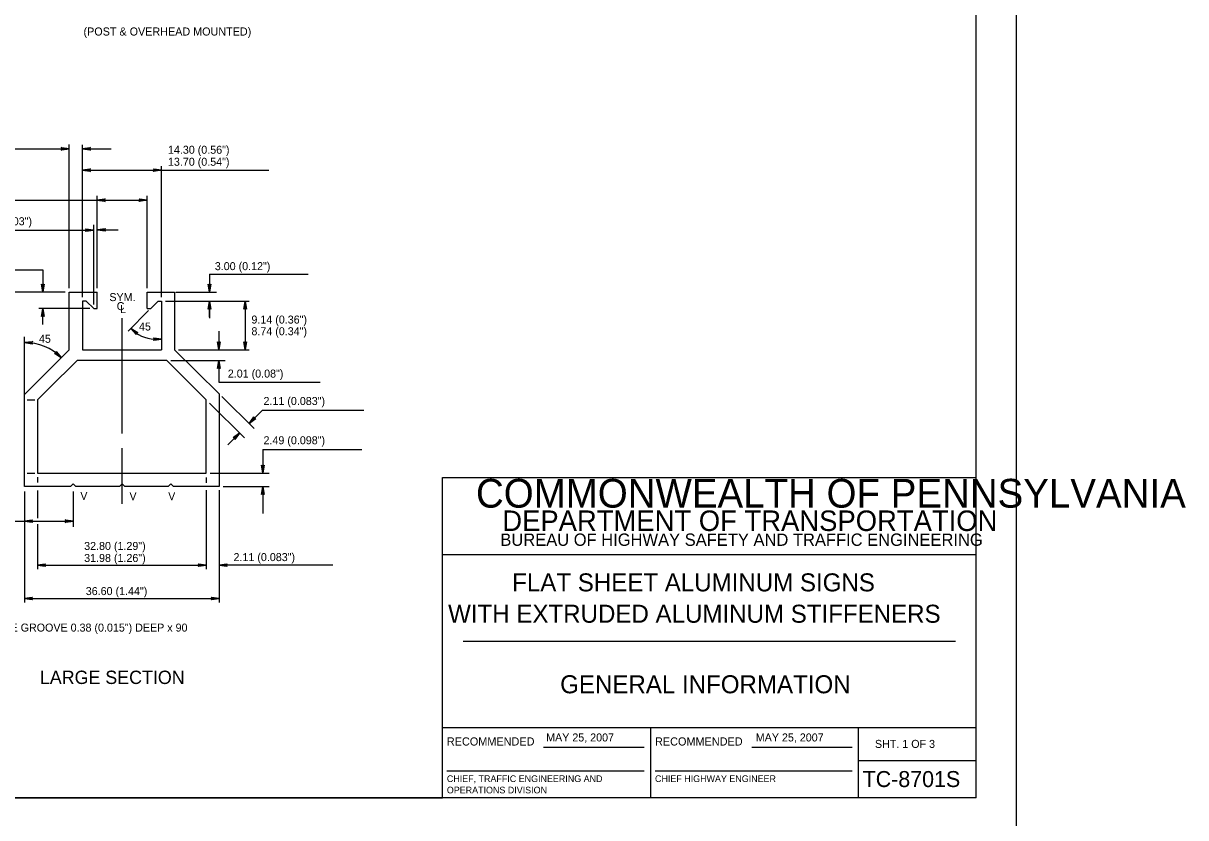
# Model space of a CAD drawing. Extents: x 650495 to 651400, y 297864 to 299646.
# Drawn here: x 650964.3 to 651399.9, y 299059.1 to 299356.9 of the extents above; entities that cross this region are included whole.
import ezdxf

# ---------------------------------------------------------------- set-up
doc = ezdxf.new("R2010")
doc.units = 0
for name, color, linetype in [('1', 7, 'Continuous'), ('2', 7, 'Continuous'), ('3', 7, 'Continuous'), ('PLT-BNDY', 7, 'Continuous')]:
    doc.layers.add(name, color=color, linetype=linetype)

# ---------------------------------------------------------------- blocks, each defined once
blk = doc.blocks.new('RARROW')
at = {"layer": '3'}
blk.add_lwpolyline([(-2.2695, 0.285), (-2.184875, 0.12075), (0, 0), (-2.2695, 0.285), (-2.38575, 0.384625), (0, 0), (-2.183125, -0.108), (-2.262875, -0.2705), (0, 0), (-2.38575, -0.379125), (-2.262875, -0.2705)], dxfattribs=at)

msp = doc.modelspace()

# ---------------------------------------------------------------- linework, layer by layer
at = {"layer": '1'}
for p, q in [((651321.31, 299066.63), (651321.31, 299630.63)), ((651121.31, 299066.63), (651121.31, 299186.63)), ((651121.31, 299186.63), (651321.31, 299186.63)), ((651321.31, 299157.63), (651121.31, 299157.63)), ((651129.06, 299125.31), (651313.56, 299125.31)), ((651121.31, 299093), (651321.31, 299093)), ((651199.31, 299093), (651199.31, 299066.63)), ((651277.19, 299066.63), (651277.19, 299093)), ((651159.24, 299085.57), (651196.87, 299085.57)), ((651237.24, 299085.57), (651274.87, 299085.57)), ((651277.19, 299080.63), (651321.31, 299080.63)), ((651122.99, 299076.68), (651196.87, 299076.68)), ((651200.99, 299076.68), (651274.87, 299076.68)), ((651321.31, 299066.63), (650535.31, 299066.63)), ((650535.31, 299066.63), (651121.31, 299066.63))]:
    msp.add_line(p, q, dxfattribs=at)
at = {"layer": '2'}
for p, q in [((650939.78, 299309.88), (650981.53, 299309.88)), ((650981.53, 299257.65), (650981.53, 299311.45)), ((650986.41, 299254.27), (650986.41, 299311.36)), ((650986.41, 299309.88), (650997.19, 299309.88)), ((650986.41, 299301.9), (651056.34, 299301.9)), ((651016.03, 299254.27), (651016.03, 299303.4)), ((650941.38, 299290.65), (651010.66, 299290.65)), ((650991.91, 299257.65), (650991.91, 299292.17)), ((651010.66, 299257.65), (651010.66, 299292.17)), ((650945.72, 299279.38), (650990.57, 299279.38)), ((650990.66, 299251.52), (650990.66, 299281.35)), ((650992.09, 299279.48), (650999.82, 299279.48)), ((650935.67, 299264.51), (650971.55, 299264.51)), ((650971.55, 299264.51), (650971.55, 299256.15)), ((651034.07, 299262.9), (651034.07, 299256.15)), ((651034.07, 299262.9), (651071.04, 299262.9)), ((650980.03, 299256.15), (650930.42, 299256.15)), ((650980.03, 299256.15), (650970.05, 299256.15)), ((650981.53, 299234.52), (650981.53, 299256.15)), ((650981.53, 299256.15), (650991.91, 299256.15)), ((650991.91, 299250.02), (650991.91, 299256.15)), ((651010.66, 299256.15), (651020.91, 299256.15)), ((651010.66, 299250.02), (651010.66, 299256.15)), ((651020.91, 299256.15), (651020.91, 299234.52)), ((651021.41, 299256.15), (651036.63, 299256.15)), ((650989.16, 299250.02), (650970.05, 299250.02)), ((650971.55, 299244.02), (650971.55, 299250.02)), ((650986.41, 299252.77), (650986.41, 299234.52)), ((650987.78, 299252.77), (650986.41, 299252.77)), ((650987.78, 299252.77), (650990.66, 299250.02)), ((650990.66, 299250.02), (650991.91, 299250.02)), ((651011.26, 299249.24), (651003.54, 299241.5)), ((651010.66, 299250.02), (651012.04, 299250.02)), ((651014.78, 299252.77), (651012.04, 299250.02)), ((651014.78, 299252.77), (651016.03, 299252.77)), ((651016.03, 299252.77), (651016.03, 299234.52)), ((651017.53, 299252.77), (651048.98, 299252.77)), ((651034.07, 299246.77), (651034.07, 299252.77)), ((651034.07, 299252.77), (651034.07, 299246.33)), ((651047.42, 299252.77), (651047.42, 299234.52)), ((651001.28, 299203.15), (651001.28, 299246.34)), ((651037.58, 299241.55), (651037.58, 299234.52)), ((650964.78, 299217.77), (650964.78, 299239.4)), ((651013.4, 299238.53), (651016.03, 299238.53)), ((650964.78, 299217.77), (650981.53, 299234.52)), ((650986.41, 299234.52), (650999.16, 299234.52)), ((651001.28, 299234.52), (651007.78, 299234.52)), ((651007.78, 299234.52), (651016.03, 299234.52)), ((651020.91, 299234.52), (651037.66, 299218.02)), ((651022.41, 299234.52), (651048.98, 299234.52)), ((651039.08, 299234.52), (651039.96, 299234.52)), ((651019.53, 299230.52), (651039.96, 299230.52)), ((651037.58, 299230.52), (651037.58, 299222.4)), ((651037.58, 299222.4), (651075.56, 299222.4)), ((650964.78, 299183.27), (650964.78, 299217.77)), ((650965.78, 299215.77), (650968.66, 299215.77)), ((651034.03, 299214.52), (651047.2, 299201.57)), ((651037.66, 299218.02), (651037.66, 299183.27)), ((651038.66, 299217.02), (651050.84, 299205.03)), ((651048.93, 299206.92), (651053.91, 299211.9)), ((651053.91, 299211.9), (651091.88, 299211.9)), ((651040.91, 299198.9), (651045.37, 299203.36)), ((651001.28, 299176.77), (651001.28, 299197.65)), ((651054.09, 299197.15), (651091.1, 299197.15)), ((651054.09, 299197.15), (651054.09, 299188.27)), ((650965.78, 299188.27), (650968.66, 299188.27)), ((651034.28, 299188.27), (651055.59, 299188.27)), ((651055.59, 299188.27), (651056.47, 299188.27)), ((650969.66, 299186.82), (650969.66, 299184.84)), ((650983.03, 299184.27), (650982.03, 299183.27)), ((650984.03, 299183.27), (650983.03, 299184.27)), ((651000.28, 299183.27), (651001.28, 299184.27)), ((651001.28, 299184.27), (651000.28, 299183.27)), ((651002.28, 299183.27), (651001.28, 299184.27)), ((651018.53, 299183.27), (651019.53, 299184.27)), ((651019.53, 299184.27), (651018.53, 299183.27)), ((651019.53, 299184.27), (651020.53, 299183.27)), ((651020.53, 299183.27), (651019.53, 299184.27)), ((651032.78, 299186.66), (651032.78, 299184.62)), ((650982.03, 299183.27), (650964.78, 299183.27)), ((650964.78, 299181.46), (650964.78, 299139.77)), ((650969.66, 299181.78), (650969.66, 299171.39)), ((650983.03, 299181.37), (650983.03, 299168.17)), ((651000.28, 299183.27), (650984.03, 299183.27)), ((651018.53, 299183.27), (651002.28, 299183.27)), ((651037.66, 299183.27), (651020.53, 299183.27)), ((651032.78, 299181.85), (651032.78, 299152.27)), ((651037.66, 299181.93), (651037.66, 299139.77)), ((651037.66, 299181.22), (651037.66, 299152.27)), ((651039.16, 299183.27), (651056.47, 299183.27)), ((651054.09, 299183.27), (651054.09, 299173.21)), ((650926.56, 299170.3), (650983.03, 299170.3)), ((651032.78, 299173.77), (651032.78, 299152.27)), ((650969.66, 299169.19), (650969.66, 299152.27)), ((650969.66, 299153.77), (651032.78, 299153.77)), ((651026.78, 299153.77), (651032.78, 299153.77)), ((651080.25, 299153.77), (651037.66, 299153.77)), ((650964.78, 299141.27), (651037.66, 299141.27))]:
    msp.add_line(p, q, dxfattribs=at)
for points in [[(650999.16, 299234.52), (651001.28, 299234.52)], [(650984.53, 299230.52), (650973.78, 299219.9)], [(650999.16, 299230.52), (650984.53, 299230.52)], [(651001.28, 299230.52), (650999.16, 299230.52)], [(651007.78, 299230.52), (651001.28, 299230.52)], [(651018.03, 299230.52), (651007.78, 299230.52)], [(651023.78, 299224.77), (651018.03, 299230.52)], [(651032.78, 299200.15), (651032.78, 299215.77), (651023.78, 299224.77)], [(650973.78, 299219.9), (650969.66, 299215.77), (650969.66, 299188.27), (650973.78, 299188.27)], [(651007.78, 299188.27), (651032.78, 299188.27), (651032.78, 299200.15)], [(650973.78, 299188.27), (651001.28, 299188.27)], [(651001.28, 299188.27), (651005.91, 299188.27)], [(651005.91, 299188.27), (651007.78, 299188.27)]]:
    msp.add_lwpolyline(points, dxfattribs=at)
for centre, radius, start, end in [((651014, 299251.58), 13.06, 223.8098, 267.3752), ((650964.78, 299217.77), 19.5, 45, 90)]:
    msp.add_arc(centre, radius, start, end, dxfattribs=at)
at = {"layer": 'PLT-BNDY'}
msp.add_lwpolyline([(650495.31, 299645.63), (651336.31, 299645.63), (651336.31, 299051.63), (650495.31, 299051.63)], close=True, dxfattribs=at)

# ---------------------------------------------------------------- block references
at = {"layer": '2', "xscale": 1.2574347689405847, "yscale": 1.3092961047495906}
for p in [(650981.53, 299309.88), (651016.03, 299301.9), (651010.66, 299290.65), (650990.57, 299279.38), (651016.03, 299238.53), (650983.03, 299170.3), (651032.78, 299153.77), (651037.66, 299141.27)]:
    msp.add_blockref('RARROW', p, dxfattribs=at)
at = {"layer": '2'}
for p, xscale, yscale, rotation in [((650986.41, 299309.88), 1.2574347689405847, 1.3092961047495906, 180), ((650986.41, 299301.9), 1.2574347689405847, 1.3092961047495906, 180), ((650991.91, 299290.65), 1.2574347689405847, 1.3092961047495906, 180), ((650992.09, 299279.48), 1.2574347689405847, 1.3092961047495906, 180), ((650971.55, 299256.15), 1.2574347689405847, 1.3092961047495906, -90.00000000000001), ((651034.07, 299256.15), 1.2574347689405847, 1.3092961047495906, -90.00000000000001), ((650971.55, 299250.02), 1.2574347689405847, 1.3092961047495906, 89.99999999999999), ((651034.07, 299252.77), 1.2574347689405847, 1.3092961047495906, 89.99999999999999), ((651047.42, 299252.77), 1.2574347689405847, 1.3092961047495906, 89.99999999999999), ((651004.57, 299242.54), 1.2574347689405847, 1.3092961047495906, 140.9194989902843), ((650964.78, 299237.27), 1.2574347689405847, 1.3092961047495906, 176.80414646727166), ((651037.58, 299234.52), 1.2574347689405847, 1.3092961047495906, -90.00000000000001), ((651047.42, 299234.52), 1.2574347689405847, 1.3092961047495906, -90.00000000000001), ((650978.57, 299231.56), 1.2574347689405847, 1.3092961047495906, -40.89957129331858), ((651037.58, 299230.52), 1.2574347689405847, 1.3092961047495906, 89.99999999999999), ((651048.93, 299206.89), 1.2574347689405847, 1.3092961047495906, -134.02087905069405), ((651045.37, 299203.36), 1.2574347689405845, 1.3092961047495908, 44.7961575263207), ((651054.09, 299188.27), 1.2574347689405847, 1.3092961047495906, -90.00000000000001), ((651054.09, 299183.27), 1.2574347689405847, 1.3092961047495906, 89.99999999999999), ((650964.78, 299170.3), 1.2574347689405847, 1.3092961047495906, 180), ((650969.66, 299153.77), 1.2574347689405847, 1.3092961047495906, 180), ((651037.66, 299153.77), 1.2574347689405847, 1.3092961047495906, 180), ((650964.78, 299141.27), 1.2574347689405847, 1.3092961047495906, 180)]:
    msp.add_blockref('RARROW', p, dxfattribs=dict(at, xscale=xscale, yscale=yscale, rotation=rotation))

# ---------------------------------------------------------------- texts
at = {"layer": '1'}
for s, height, p in [('COMMONWEALTH OF PENNSYLVANIA', 10.7828, (651133.9, 299175.36)), ('DEPARTMENT OF TRANSPORTATION', 7.6837, (651143.76, 299166.61)), ('BUREAU OF HIGHWAY SAFETY AND TRAFFIC ENGINEERING', 4.6253, (651143.04, 299161.04)), ('FLAT SHEET ALUMINUM SIGNS', 6.75, (651147.47, 299143.97)), ('WITH EXTRUDED ALUMINUM STIFFENERS', 6.75, (651123.47, 299132.22)), ('GENERAL INFORMATION', 6.75, (651165.45, 299105.78)), ('RECOMMENDED', 3.048, (651122.99, 299086.2)), ('RECOMMENDED', 3.048, (651200.99, 299086.2)), ('SHT. 1 OF 3', 3, (651283.4, 299085.31)), ('CHIEF, TRAFFIC ENGINEERING AND', 2.5, (651122.99, 299072.51)), ('CHIEF HIGHWAY ENGINEER', 2.5, (651200.99, 299072.51)), ('TC-8701S', 6, (651278.79, 299070.63)), ('OPERATIONS DIVISION', 2.5, (651122.99, 299068.26))]:
    msp.add_text(s, height=height, dxfattribs=at).set_placement(p)
at = {"layer": '2'}
for s, height, p in [('(POST & OVERHEAD MOUNTED)', 3.0217, (650986.85, 299352.31)), ('14.30 (0.56")', 3, (651018.49, 299308)), ('13.70 (0.54")', 3, (651018.49, 299303.5)), ('0.74 (0.03")', 3, (650946.72, 299281.2)), ('3.00 (0.12")', 3, (651036.04, 299264.37)), ('SYM.', 3, (650996.53, 299252.77)), ('C', 3, (650999.28, 299249.4)), ('L', 3, (651000.53, 299248.27)), ('45', 3, (651007.65, 299241.75)), ('9.14 (0.36")', 3, (651049.77, 299244.35)), ('45', 3, (650970.16, 299237.15)), ('8.74 (0.34")', 3, (651049.77, 299239.98)), ('2.01 (0.08")', 3, (651040.92, 299224.11)), ('2.11 (0.083")', 3, (651054.3, 299213.83)), ('2.49 (0.098")', 3, (651054.3, 299199.11)), ('V', 3, (650985.65, 299178.27)), ('V', 3, (651004.06, 299178.15)), ('V', 3, (651018.57, 299178.15)), ('32.80 (1.29")', 3, (650987.09, 299159.5)), ('31.98 (1.26")', 3, (650987.09, 299155)), ('2.11 (0.083")', 3, (651043.06, 299155.32)), ('36.60 (1.44")', 3, (650987.69, 299142.59)), ('V = VEE GROOVE 0.38 (0.015") DEEP x 90', 3, (650946.91, 299128.9)), ('LARGE SECTION', 5, (650970.5, 299109.26)), ('MAY 25, 2007', 3, (651160.2, 299087.73)), ('MAY 25, 2007', 3, (651238.75, 299087.73))]:
    msp.add_text(s, height=height, dxfattribs=at).set_placement(p)

doc.saveas('drawing.dxf')
